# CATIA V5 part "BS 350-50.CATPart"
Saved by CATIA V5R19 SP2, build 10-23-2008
Part number: BS 300-50
Bounding box of the stored display mesh (mm): x -15.868 to 15.868, y -15.868 to 15.868, z 0 to 130
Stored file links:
  C:\Users\Bora\Desktop\3D Katı model\BS serisi\BS 300\BS 300-50.CATPart
  C:\Program Files\Dassault Systemes\B19\intel_a\reffiles\standard\MetricThickPitch.txt
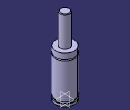
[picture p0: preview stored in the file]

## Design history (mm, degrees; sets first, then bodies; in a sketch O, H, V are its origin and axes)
Body1 (main body)
  Sketch1 on yz-plane, origin (0, 0, 0), H (0, 1, 0), V (0, 0, 1)
    point P1 (8, 129)
    point P3 (8, 129)
    point P5 (16, 69.5)
    point P6 (16, 67.5)
    point P9 (16, 69.5)
    point P14 (16, 67.5)
    line L1 (8, 129) -> (8, 79)
    arc A1 centre (7, 129) radius 1 from (8, 129) to (7, 130) ccw
    arc A2 centre (16, 68.5) radius 1 from (16, 69.5) to (16, 67.5) ccw
    line L2 (16, 0) -> (16, 4)
    line L3 (16, 69.5) -> (16, 79)
    line L4 (14.5, 7.5) -> (14.5, 4)
    line L5 (16, 7.5) -> (16, 67.5)
    line L6 (7, 130) -> (0, 130)
    point P15 (0, 130)
    line L7 (8, 79) -> (16, 79)
    line L8 (0, 0) -> (16, 0)
    line L9 (14.5, 7.5) -> (16, 7.5)
    line L10 (14.5, 4) -> (16, 4)
    coincidence: P15 V, P1 P3, P5 P9, P6 P14
    tangency: L6 A1
    horizontal: L7 H, L8 H, L9 H, L10 H
  Shaft1: profile Sketch1, axis Sketch1.V, angle 360
  Sketch2 on face of Shaft1 from Sketch1.L8, origin (0, 0, 0), H (1, 0, 0), V (0, -1, 0)
    point P1 (0, 0)
  Hole1: placed by Sketch2, at (0, 0, 0) direction (0, 0, 1), diameter 6.647, depth 4, threaded "M8", thread diameter 8, thread depth 4, pitch 1.25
